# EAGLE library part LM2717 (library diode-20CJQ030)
National's LM2717-ADJ Dual Step-Down DC/DC Converter Description: The LM2717-ADJ is composed of two PWM DC/DC buck (step-down) converters. Both converters are used to generate an adjustable output voltage as low as 1.267V. Both also feature low RDSON (0.16?) internal switches for maximum efficiency. Operating frequency can be adjusted anywhere between 300kHz and 600kHz allowing the use of small external components. External soft-start pins for each converter enables the user to tailor the soft-start times to a specific application. Each converter may also be shut down independently with its own shutdown pin. The LM2717-ADJ is available in a low profile 24-lead TSSOP package ensuring a low profile overall solution. Features: Adjustable buck converter with a 2.2A, 0.16?, internal switch (Buck 1) Adjustable buck converter with a 3.2A, 0.16?, internal switch (Buck 2) Operating input voltage range of 4V to 20V Input undervoltage protection 300kHz to 600kHz pin adjustable operating frequency Over temperature protection Small 24-Lead TSSOP package Applications: TFT-LCD Displays Handheld Devices Portable Applications Laptop Computers Automotive Applications Please send any comments to: messi@users.sourceforge.net
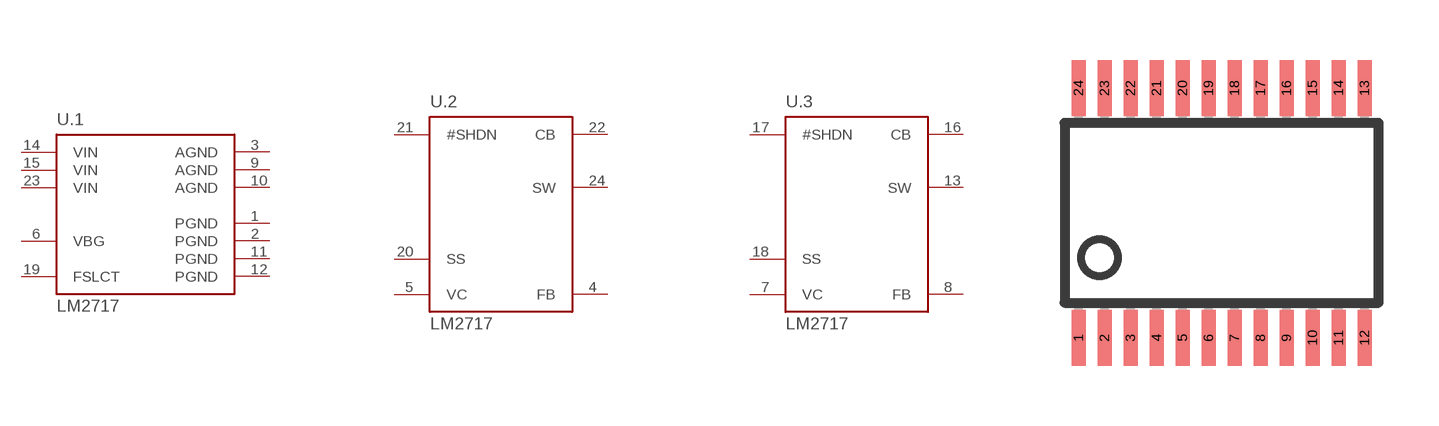
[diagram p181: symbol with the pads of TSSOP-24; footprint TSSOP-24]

Designator prefix U; gates .1=LM2717_PWR .2=LM2717 .3=LM2717

## LM2717  [TSSOP-24]
1  .1:PGND  pwr
2  .1:PGND  pwr
3  .1:AGND  pwr
4  .2:FB  in
5  .2:VC  in
6  .1:VBG  in
7  .3:VC  in
8  .3:FB  in
9  .1:AGND  pwr
10  .1:AGND  pwr
11  .1:PGND  pwr
12  .1:PGND  pwr
13  .3:SW  in
14  .1:VIN  pwr
15  .1:VIN  pwr
16  .3:CB  in
17  .3:#SHDN  pas
18  .3:SS  in
19  .1:FSLCT  in
20  .2:SS  in
21  .2:#SHDN  pas
22  .2:CB  in
23  .1:VIN  pwr
24  .2:SW  in

## Footprint TSSOP-24 (pad centres in mm)
TSSOP-24 4.5mm body ie. bq24702/3
smd 0.35 x 1.4: 1 -3.725,-3.125; 2 -3.075,-3.125; 3 -2.425,-3.125; 4 -1.775,-3.125; 5 -1.125,-3.125; 6 -0.475,-3.125; 7 0.175,-3.125; 8 0.825,-3.125; 9 1.475,-3.125; 10 2.125,-3.125; 11 2.775,-3.125; 12 3.425,-3.125; 13 3.425,3.125; 14 2.775,3.125; 15 2.125,3.125; 16 1.475,3.125; 17 0.825,3.125; 18 0.175,3.125; 19 -0.475,3.125; 20 -1.125,3.125; 21 -1.775,3.125; 22 -2.425,3.125; 23 -3.075,3.125; 24 -3.725,3.125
